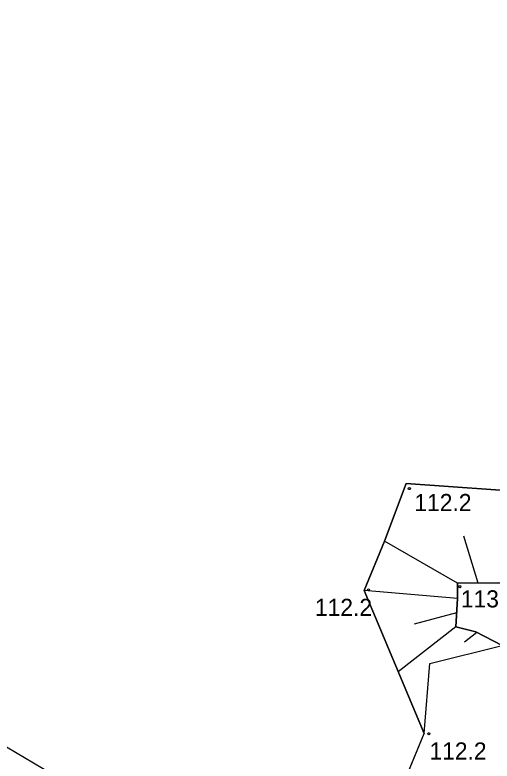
# Model space of a CAD drawing. Extents: x 6434771 to 6436222, y 5663454 to 5664782.
# Drawn here: x 6434836.74 to 6434857.69, y 5664042.15 to 5664074.89 of the extents above; entities that cross this region are included whole.
import ezdxf

# ---------------------------------------------------------------- set-up
doc = ezdxf.new("R2010")
doc.units = 0
for name, color, linetype in [('Warstwa 10', 7, 'Continuous'), ('Warstwa 11', 7, 'Continuous'), ('Warstwa 13', 7, 'Continuous'), ('Warstwa 20', 7, 'Continuous'), ('Warstwa 21', 7, 'Continuous'), ('Warstwa 63', 7, 'Continuous'), ('Warstwa 9', 7, 'Continuous')]:
    doc.layers.add(name, color=color, linetype=linetype)

msp = doc.modelspace()

# ---------------------------------------------------------------- linework, layer by layer
at = {"layer": 'Warstwa 10'}
for p, q in [((6434854.964, 5664046.429), (6434858.133, 5664047.22)), ((6434854.707, 5664043.362), (6434854.964, 5664046.429)), ((6434853.244, 5664039.819), (6434854.707, 5664043.362))]:
    msp.add_line(p, q, dxfattribs=at)
at = {"layer": 'Warstwa 11'}
msp.add_lwpolyline([(6434851.167, 5664034.04), (6434853.244, 5664039.819), (6434854.707, 5664043.362), (6434852.082, 5664049.633), (6434852.968, 5664051.803), (6434853.919, 5664054.321), (6434859.705, 5664053.921), (6434860.738, 5664054.998), (6434863.166, 5664060.762), (6434865.974, 5664067.104), (6434866.565, 5664067.707), (6434867.374, 5664068.572), (6434873.102, 5664069.709), (6434878.457, 5664070.631), (6434879.06, 5664070.809), (6434879.426, 5664100.89), (6434877.935, 5664101.425), (6434879.465, 5664104.305), (6434880.206, 5664165.364)], dxfattribs=at)
at = {"layer": 'Warstwa 13'}
for centre in [(6434854.06, 5664054.101), (6434852.266, 5664049.659), (6434856.276, 5664049.8), (6434854.913, 5664043.347)]:
    msp.add_circle(centre, 0.045, dxfattribs=at)
at = {"layer": 'Warstwa 20'}
msp.add_lwpolyline([(6434861.403, 5664049.62), (6434857.987, 5664049.962), (6434856.176, 5664049.954), (6434856.168, 5664049.274), (6434856.103, 5664048.035), (6434856.981, 5664047.814), (6434858.133, 5664047.22)], dxfattribs=at)
at = {"layer": 'Warstwa 21'}
for p, q in [((6434854.964, 5664046.429), (6434858.133, 5664047.22)), ((6434854.707, 5664043.362), (6434854.964, 5664046.429)), ((6434853.244, 5664039.819), (6434854.707, 5664043.362))]:
    msp.add_line(p, q, dxfattribs=at)
msp.add_lwpolyline([(6434854.707, 5664043.362), (6434852.082, 5664049.633), (6434852.968, 5664051.803), (6434853.919, 5664054.321), (6434859.705, 5664053.921), (6434860.738, 5664054.998)], dxfattribs=at)
at = {"layer": 'Warstwa 63'}
msp.add_lwpolyline([(6435677.2, 5663546.629), (6436084.093, 5664236.205), (6435222.122, 5664744.822), (6434815.229, 5664055.245)], close=True, dxfattribs=at)
at = {"layer": 'Warstwa 9'}
for p, q in [((6434857.076, 5664049.958), (6434856.458, 5664052.015)), ((6434856.176, 5664049.954), (6434852.968, 5664051.803)), ((6434856.168, 5664049.274), (6434852.082, 5664049.633)), ((6434856.136, 5664048.65), (6434854.274, 5664048.149)), ((6434856.103, 5664048.035), (6434853.576, 5664046.063)), ((6434857.022, 5664047.793), (6434856.478, 5664047.366))]:
    msp.add_line(p, q, dxfattribs=at)
msp.add_lwpolyline([(6434860.738, 5664054.998), (6434859.705, 5664053.921), (6434853.919, 5664054.321), (6434852.968, 5664051.803), (6434852.082, 5664049.633), (6434854.707, 5664043.362), (6434854.964, 5664046.429), (6434858.133, 5664047.22), (6434856.981, 5664047.814), (6434856.103, 5664048.035), (6434856.168, 5664049.274), (6434856.176, 5664049.954), (6434857.987, 5664049.962), (6434861.403, 5664049.62)], close=True, dxfattribs=at)

# ---------------------------------------------------------------- texts
at = {"layer": 'Warstwa 13'}
for s, p in [('112.2', (6434854.28, 5664053.118)), ('113.6', (6434856.322, 5664048.888)), ('112.2', (6434849.913, 5664048.518)), ('112.2', (6434854.942, 5664042.215))]:
    msp.add_text(s, height=0.75, dxfattribs=at).set_placement(p)

doc.saveas('drawing.dxf')
